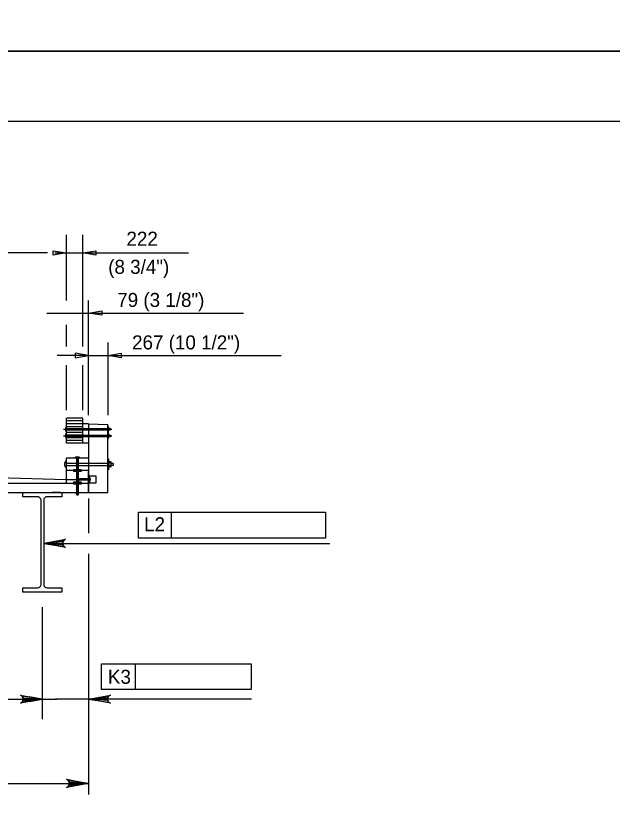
# Model space of a CAD drawing. Extents: x 638175 to 640495, y 294277 to 298435.
# Drawn here: x 638679.7 to 638806.9, y 296491.5 to 296661 of the extents above; entities that cross this region are included whole.
import ezdxf

# ---------------------------------------------------------------- set-up
doc = ezdxf.new("R2010")
doc.units = 0
for name, color, linetype in [('2', 7, 'Continuous'), ('3', 7, 'Continuous'), ('4', 7, 'Continuous'), ('6', 7, 'Continuous'), ('PLT-BNDY', 7, 'Continuous')]:
    doc.layers.add(name, color=color, linetype=linetype)

msp = doc.modelspace()

# ---------------------------------------------------------------- linework, layer by layer
at = {"layer": '2'}
for p, q in [((638475.46, 296638.46), (639261.46, 296638.46)), ((638690.48, 296600.26), (638690.48, 296614.24)), ((638693.95, 296590.38), (638693.95, 296614.24)), ((638686.45, 296610.39), (638559.36, 296610.39)), ((638688.04, 296610.39), (638716.53, 296610.39)), ((638695.18, 296575.77), (638695.18, 296600.26)), ((638686.28, 296597.55), (638728.25, 296597.55)), ((638690.48, 296590.38), (638690.48, 296595.03)), ((638699.35, 296591.29), (638699.35, 296575.77)), ((638695.18, 296588.49), (638688.53, 296588.49)), ((638695.18, 296588.49), (638736.33, 296588.49)), ((638690.48, 296576.86), (638690.48, 296586.46)), ((638693.95, 296576.86), (638693.95, 296586.46)), ((638693.95, 296575.14), (638690.48, 296575.14)), ((638690.48, 296569.78), (638690.48, 296575.14)), ((638693.95, 296574.55), (638690.48, 296574.55)), ((638693.95, 296573.95), (638690.48, 296573.95)), ((638693.95, 296569.78), (638693.95, 296575.14)), ((638695.18, 296573.95), (638693.95, 296573.95)), ((638695.18, 296573.95), (638699.35, 296573.76)), ((638695.18, 296573.95), (638695.18, 296566.61)), ((638695.18, 296573.95), (638699.35, 296573.76)), ((638699.35, 296559.29), (638699.35, 296573.76)), ((638690.48, 296573.36), (638693.95, 296573.36)), ((638690.48, 296572.91), (638699.35, 296572.91)), ((638690.48, 296572.62), (638699.35, 296572.62)), ((638690.48, 296572.17), (638693.95, 296572.17)), ((638699.45, 296573.36), (638699.35, 296573.36)), ((638699.35, 296572.17), (638699.35, 296572.17)), ((638699.35, 296572.17), (638699.45, 296572.17)), ((638699.45, 296572.17), (638699.45, 296573.36)), ((638699.45, 296572.53), (638699.45, 296572.99)), ((638699.65, 296572.99), (638699.45, 296572.99)), ((638699.65, 296572.87), (638699.45, 296572.87)), ((638699.65, 296572.64), (638699.45, 296572.64)), ((638699.65, 296572.53), (638699.45, 296572.53)), ((638699.45, 296572.17), (638699.45, 296572.17)), ((638699.68, 296572.93), (638699.68, 296572.59)), ((638699.68, 296572.93), (638699.68, 296572.59)), ((638699.68, 296572.91), (638699.86, 296572.91)), ((638699.68, 296572.61), (638699.86, 296572.61)), ((638699.89, 296572.88), (638699.86, 296572.91)), ((638699.89, 296572.63), (638699.86, 296572.61)), ((638699.89, 296572.88), (638699.89, 296572.63)), ((638690.48, 296571.57), (638693.95, 296571.57)), ((638690.48, 296571.52), (638699.35, 296571.52)), ((638690.48, 296571.22), (638699.35, 296571.22)), ((638690.48, 296570.98), (638693.95, 296570.98)), ((638693.95, 296570.38), (638690.48, 296570.38)), ((638699.45, 296571.97), (638699.35, 296571.97)), ((638699.35, 296570.77), (638699.35, 296570.77)), ((638699.35, 296570.77), (638699.45, 296570.77)), ((638699.45, 296570.77), (638699.45, 296571.97)), ((638699.45, 296571.14), (638699.45, 296571.6)), ((638699.65, 296571.6), (638699.45, 296571.6)), ((638699.65, 296571.48), (638699.45, 296571.48)), ((638699.65, 296571.25), (638699.45, 296571.25)), ((638699.65, 296571.14), (638699.45, 296571.14)), ((638699.45, 296570.77), (638699.45, 296570.77)), ((638699.68, 296571.54), (638699.68, 296571.2)), ((638699.68, 296571.54), (638699.68, 296571.2)), ((638699.68, 296571.52), (638699.86, 296571.52)), ((638699.68, 296571.22), (638699.86, 296571.22)), ((638699.89, 296571.5), (638699.86, 296571.52)), ((638699.89, 296571.25), (638699.86, 296571.22)), ((638699.89, 296571.5), (638699.89, 296571.25)), ((638695.18, 296569.78), (638690.48, 296569.78)), ((638695.18, 296566.61), (638690.42, 296566.61)), ((638690.42, 296566.61), (638690.42, 296563.93)), ((638690.42, 296565.51), (638699.35, 296565.51)), ((638692.66, 296566.61), (638692.66, 296559.29)), ((638692.8, 296558.78), (638692.8, 296566.96)), ((638692.96, 296566.61), (638692.96, 296559.29)), ((638695.18, 296566.61), (638695.18, 296563.93)), ((638699.35, 296566.46), (638699.35, 296564.08)), ((638699.35, 296566.46), (638699.45, 296566.46)), ((638699.35, 296565.54), (638699.45, 296565.54)), ((638699.45, 296566.46), (638699.45, 296564.08)), ((638699.45, 296565.82), (638699.45, 296564.72)), ((638699.94, 296565.82), (638699.45, 296565.82)), ((638699.95, 296565.54), (638699.45, 296565.54)), ((638700.04, 296564.86), (638700.04, 296565.68)), ((638700.04, 296565.51), (638700.04, 296565.51)), ((638700.04, 296565.51), (638700.44, 296565.51)), ((638700.48, 296565.47), (638700.44, 296565.51)), ((638700.48, 296565.47), (638700.48, 296565.07)), ((638690.42, 296565.02), (638699.35, 296565.02)), ((638690.42, 296563.93), (638690.42, 296561.25)), ((638695.18, 296563.93), (638690.42, 296563.93)), ((638692.01, 296564.13), (638692.01, 296563.73)), ((638693.6, 296564.13), (638692.01, 296564.13)), ((638693.6, 296563.73), (638692.01, 296563.73)), ((638693.6, 296564.13), (638693.6, 296563.73)), ((638695.18, 296563.93), (638695.18, 296561.25)), ((638699.35, 296565), (638699.45, 296565)), ((638699.45, 296564.08), (638699.35, 296564.08)), ((638699.95, 296565), (638699.45, 296565)), ((638699.94, 296564.72), (638699.45, 296564.72)), ((638700.44, 296565.02), (638700.04, 296565.02)), ((638700.48, 296565.07), (638700.44, 296565.02)), ((638690.42, 296562.06), (638695.18, 296562.06)), ((638693.04, 296562.04), (638693.26, 296562.16)), ((638693.04, 296562.04), (638693.26, 296561.91)), ((638695.37, 296562.16), (638693.26, 296562.16)), ((638695.37, 296561.91), (638693.26, 296561.91)), ((638695.18, 296562.84), (638696.78, 296562.84)), ((638695.37, 296562.84), (638695.37, 296561.25)), ((638695.43, 296562.34), (638695.37, 296562.34)), ((638695.43, 296562.34), (638695.43, 296561.74)), ((638695.43, 296562.24), (638695.57, 296562.24)), ((638695.57, 296562.24), (638695.57, 296561.85)), ((638696.78, 296562.84), (638696.78, 296561.25)), ((638692.01, 296561.45), (638692.01, 296561.05)), ((638693.6, 296561.45), (638692.01, 296561.45)), ((638693.6, 296561.05), (638692.01, 296561.05)), ((638693.6, 296561.45), (638693.6, 296561.05)), ((638696.78, 296561.25), (638695.18, 296561.25)), ((638695.18, 296561.25), (638695.18, 296559.29)), ((638695.43, 296561.74), (638695.37, 296561.74)), ((638695.43, 296561.85), (638695.57, 296561.85)), ((638692.21, 296559.19), (638692.21, 296559.29)), ((638693.41, 296559.19), (638692.21, 296559.19)), ((638692.57, 296558.99), (638692.57, 296559.19)), ((638692.63, 296559.29), (638692.63, 296559.19)), ((638692.63, 296558.96), (638692.98, 296558.96)), ((638692.66, 296558.96), (638692.66, 296558.78)), ((638692.68, 296558.76), (638692.66, 296558.78)), ((638692.93, 296558.93), (638692.68, 296558.93)), ((638692.93, 296558.91), (638692.68, 296558.91)), ((638692.93, 296558.88), (638692.68, 296558.88)), ((638692.93, 296558.86), (638692.68, 296558.86)), ((638692.93, 296558.83), (638692.68, 296558.83)), ((638692.93, 296558.8), (638692.68, 296558.8)), ((638692.93, 296558.78), (638692.68, 296558.78)), ((638692.68, 296558.76), (638692.93, 296558.76)), ((638692.69, 296558.99), (638692.69, 296559.19)), ((638692.92, 296558.99), (638692.92, 296559.19)), ((638692.93, 296558.76), (638692.96, 296558.78)), ((638692.96, 296558.96), (638692.96, 296558.78)), ((638692.99, 296559.29), (638692.99, 296559.19)), ((638693.03, 296558.99), (638693.03, 296559.19)), ((638693.41, 296559.29), (638693.41, 296559.29)), ((638693.41, 296559.29), (638693.41, 296559.19)), ((638693.41, 296559.2), (638693.41, 296559.2)), ((638695.18, 296558.01), (638695.18, 296550.61)), ((638695.18, 296546.19), (638695.18, 296494.83)), ((638685.34, 296534.79), (638685.34, 296512.32)), ((638685.34, 296521.08), (638685.34, 296510.92)), ((638553.45, 296515.17), (638688.41, 296515.17)), ((638729.95, 296515.17), (638688.18, 296515.17)), ((638553.45, 296497.2), (638695.18, 296497.2)), ((638695.18, 296497.2), (638695.18, 296497.2))]:
    msp.add_line(p, q, dxfattribs=at)
for points in [[(638696.78, 296610.86), (638696.78, 296609.92), (638693.95, 296610.39)], [(638698.02, 296598.02), (638698.02, 296597.07), (638695.18, 296597.55)], [(638692.35, 296588.96), (638692.35, 296588.01), (638695.18, 296588.49)], [(638702.19, 296588.96), (638702.19, 296588.01), (638699.36, 296588.49)], [(638682.51, 296515.64), (638682.51, 296514.7), (638685.34, 296515.17)], [(638692.56, 296496.76), (638692.56, 296497.63), (638695.18, 296497.2)]]:
    msp.add_lwpolyline(points, close=True, dxfattribs=at)
for points in [[(638685.63, 296548.41), (638690.29, 296549.28), (638689.93, 296549.03), (638689.75, 296548.72), (638689.69, 296548.41), (638689.75, 296548.1), (638689.93, 296547.78), (638690.29, 296547.54), (638685.63, 296548.41), (638689.93, 296547.78), (638689.75, 296548.1), (638685.63, 296548.41), (638689.69, 296548.41), (638689.75, 296548.72), (638685.63, 296548.41), (638689.93, 296549.03)], [(638685.34, 296515.17), (638680.68, 296514.3), (638681.04, 296514.55), (638681.23, 296514.86), (638681.28, 296515.17), (638681.23, 296515.48), (638681.04, 296515.8), (638680.68, 296516.04), (638685.34, 296515.17), (638681.04, 296515.8), (638681.23, 296515.48), (638685.34, 296515.17), (638681.28, 296515.17), (638681.23, 296514.86), (638685.34, 296515.17), (638681.04, 296514.55)], [(638695.18, 296515.17), (638699.85, 296516.04), (638699.49, 296515.8), (638699.3, 296515.48), (638699.25, 296515.17), (638699.3, 296514.86), (638699.49, 296514.55), (638699.85, 296514.3), (638695.18, 296515.17), (638699.49, 296514.55), (638699.3, 296514.86), (638695.18, 296515.17), (638699.25, 296515.17), (638699.3, 296515.48), (638695.18, 296515.17), (638699.49, 296515.8)], [(638695.18, 296497.2), (638690.52, 296496.32), (638690.88, 296496.57), (638691.07, 296496.88), (638691.12, 296497.2), (638691.07, 296497.51), (638690.88, 296497.82), (638690.52, 296498.07), (638695.18, 296497.2), (638690.88, 296497.82), (638691.07, 296497.51), (638695.18, 296497.2), (638691.12, 296497.2), (638691.07, 296496.88), (638695.18, 296497.2), (638690.88, 296496.57)]]:
    msp.add_lwpolyline(points, dxfattribs=at)
for centre, radius, start, end in [((638691.14, 296572.76), 0.898, 138.5212, 221.4788), ((638699.49, 296572.76), 0.195, 323.9035, 35.4998), ((638699.62, 296572.59), 0.0631, 294.7299, 65.8765), ((638699.62, 296572.93), 0.0634, 295.2914, 65.298), ((638691.14, 296571.37), 0.898, 138.5212, 221.4788), ((638699.49, 296571.37), 0.195, 323.9035, 35.4998), ((638699.62, 296571.2), 0.0631, 294.7299, 65.8765), ((638699.62, 296571.54), 0.0634, 295.2914, 65.298), ((638690.89, 296565.27), 0.852, 123.281, 236.7201), ((638692.8, 296565.93), 0.898, 48.5212, 131.4788), ((638699.88, 296565.68), 0.151, 294.1303, 66.5922), ((638699.57, 296565.27), 0.469, 324.4913, 36.1094), ((638699.88, 296564.86), 0.152, 290.9772, 64.7169), ((638692.63, 296559.02), 0.0634, 204.702, 334.7086), ((638692.8, 296559.15), 0.195, 234.5002, 306.0965), ((638692.98, 296559.02), 0.0631, 204.1235, 335.2701)]:
    msp.add_arc(centre, radius, start, end, dxfattribs=at)
at = {"layer": '3'}
for p, q in [((638695.18, 296573.95), (638695.18, 296559.29)), ((638695.18, 296573.95), (638695.18, 296559.29)), ((638689.85, 296572.76), (638700.15, 296572.76)), ((638689.85, 296571.38), (638700.15, 296571.38)), ((638625.3, 296563.96), (638690.42, 296562.04)), ((638695.18, 296559.29), (638695.18, 296563.71)), ((638553.45, 296561.25), (638695.18, 296561.25)), ((638549.28, 296559.29), (638699.35, 296559.29)), ((638683.29, 296559.29), (638687.39, 296559.29)), ((638689.2, 296559.29), (638687.39, 296559.29)), ((638695.18, 296559.29), (638695.18, 296559.29)), ((638685.06, 296539.66), (638685.06, 296557.63)), ((638685.63, 296557.63), (638685.63, 296539.66))]:
    msp.add_line(p, q, dxfattribs=at)
for points in [[(638684.32, 296558.37), (638681.2, 296558.37), (638681.2, 296559.29), (638689.49, 296559.29), (638689.49, 296558.37), (638686.37, 296558.37)], [(638681.2, 296538), (638681.2, 296538.92), (638684.32, 296538.92)], [(638686.37, 296538.92), (638689.49, 296538.92), (638689.49, 296538), (638681.2, 296538)]]:
    msp.add_lwpolyline(points, dxfattribs=at)
for centre, start, end in [((638684.32, 296557.63), 0, 90), ((638686.37, 296557.63), 90, 180), ((638684.32, 296539.66), 270, 0), ((638686.37, 296539.66), 180, 270)]:
    msp.add_arc(centre, 0.738, start, end, dxfattribs=at)
at = {"layer": '4'}
for p, q in [((638705.87, 296555.08), (638745.74, 296555.08)), ((638705.87, 296549.55), (638705.87, 296555.08)), ((638712.92, 296549.55), (638712.92, 296555.08)), ((638745.74, 296555.08), (638745.74, 296549.55)), ((638685.63, 296548.41), (638746.67, 296548.41)), ((638745.74, 296549.55), (638705.87, 296549.55)), ((638697.93, 296522.74), (638729.88, 296522.74)), ((638697.93, 296517.2), (638697.93, 296522.74)), ((638705.21, 296517.2), (638705.21, 296522.74)), ((638729.88, 296522.74), (638729.88, 296517.2)), ((638729.88, 296517.2), (638697.93, 296517.2))]:
    msp.add_line(p, q, dxfattribs=at)
msp.add_lwpolyline([(638688.46, 296547.94), (638688.46, 296548.88), (638685.63, 296548.41)], close=True, dxfattribs=at)
at = {"layer": '6'}
msp.add_lwpolyline([(638687.64, 296609.92), (638687.64, 296610.86), (638690.48, 296610.39)], close=True, dxfattribs=at)
at = {"layer": 'PLT-BNDY'}
for points in [[(638435.46, 297247.46), (639276.46, 297247.46), (639276.46, 296653.46), (638435.46, 296653.46)], [(638435.46, 296653.46), (639276.46, 296653.46), (639276.46, 296059.46), (638435.46, 296059.46)]]:
    msp.add_lwpolyline(points, close=True, dxfattribs=at)

# ---------------------------------------------------------------- texts
at = {"layer": '4'}
for s, p in [('222', (638703.29, 296611.91)), ('(8 3/4")', (638699.4, 296605.91)), ('79 (3 1/8")', (638701.32, 296598.85)), ('267 (10 1/2")', (638704.49, 296589.79))]:
    msp.add_text(s, height=3, rotation=360, dxfattribs=at).set_placement(p)
for s, p in [('L2', (638707.05, 296550.98)), ('K3', (638699.34, 296518.44))]:
    msp.add_text(s, height=3, dxfattribs=at).set_placement(p)

doc.saveas('drawing.dxf')
